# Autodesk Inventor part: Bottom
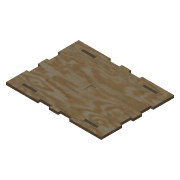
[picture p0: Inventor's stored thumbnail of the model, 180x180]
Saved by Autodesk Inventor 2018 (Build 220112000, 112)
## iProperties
Created: 2018-05
Part Number: Bottom
Material: Generic
Document SubType Name: Modeling
Designer: arivu
Density: 1 g/cm^3
Appearance: Default
Author: arivu
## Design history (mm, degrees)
derived "WaterTank.ipt"
feature "Solid2::WaterTank.ipt" dims "d0" = 10
tag "TaggingFeature1"
body "Solid1"
